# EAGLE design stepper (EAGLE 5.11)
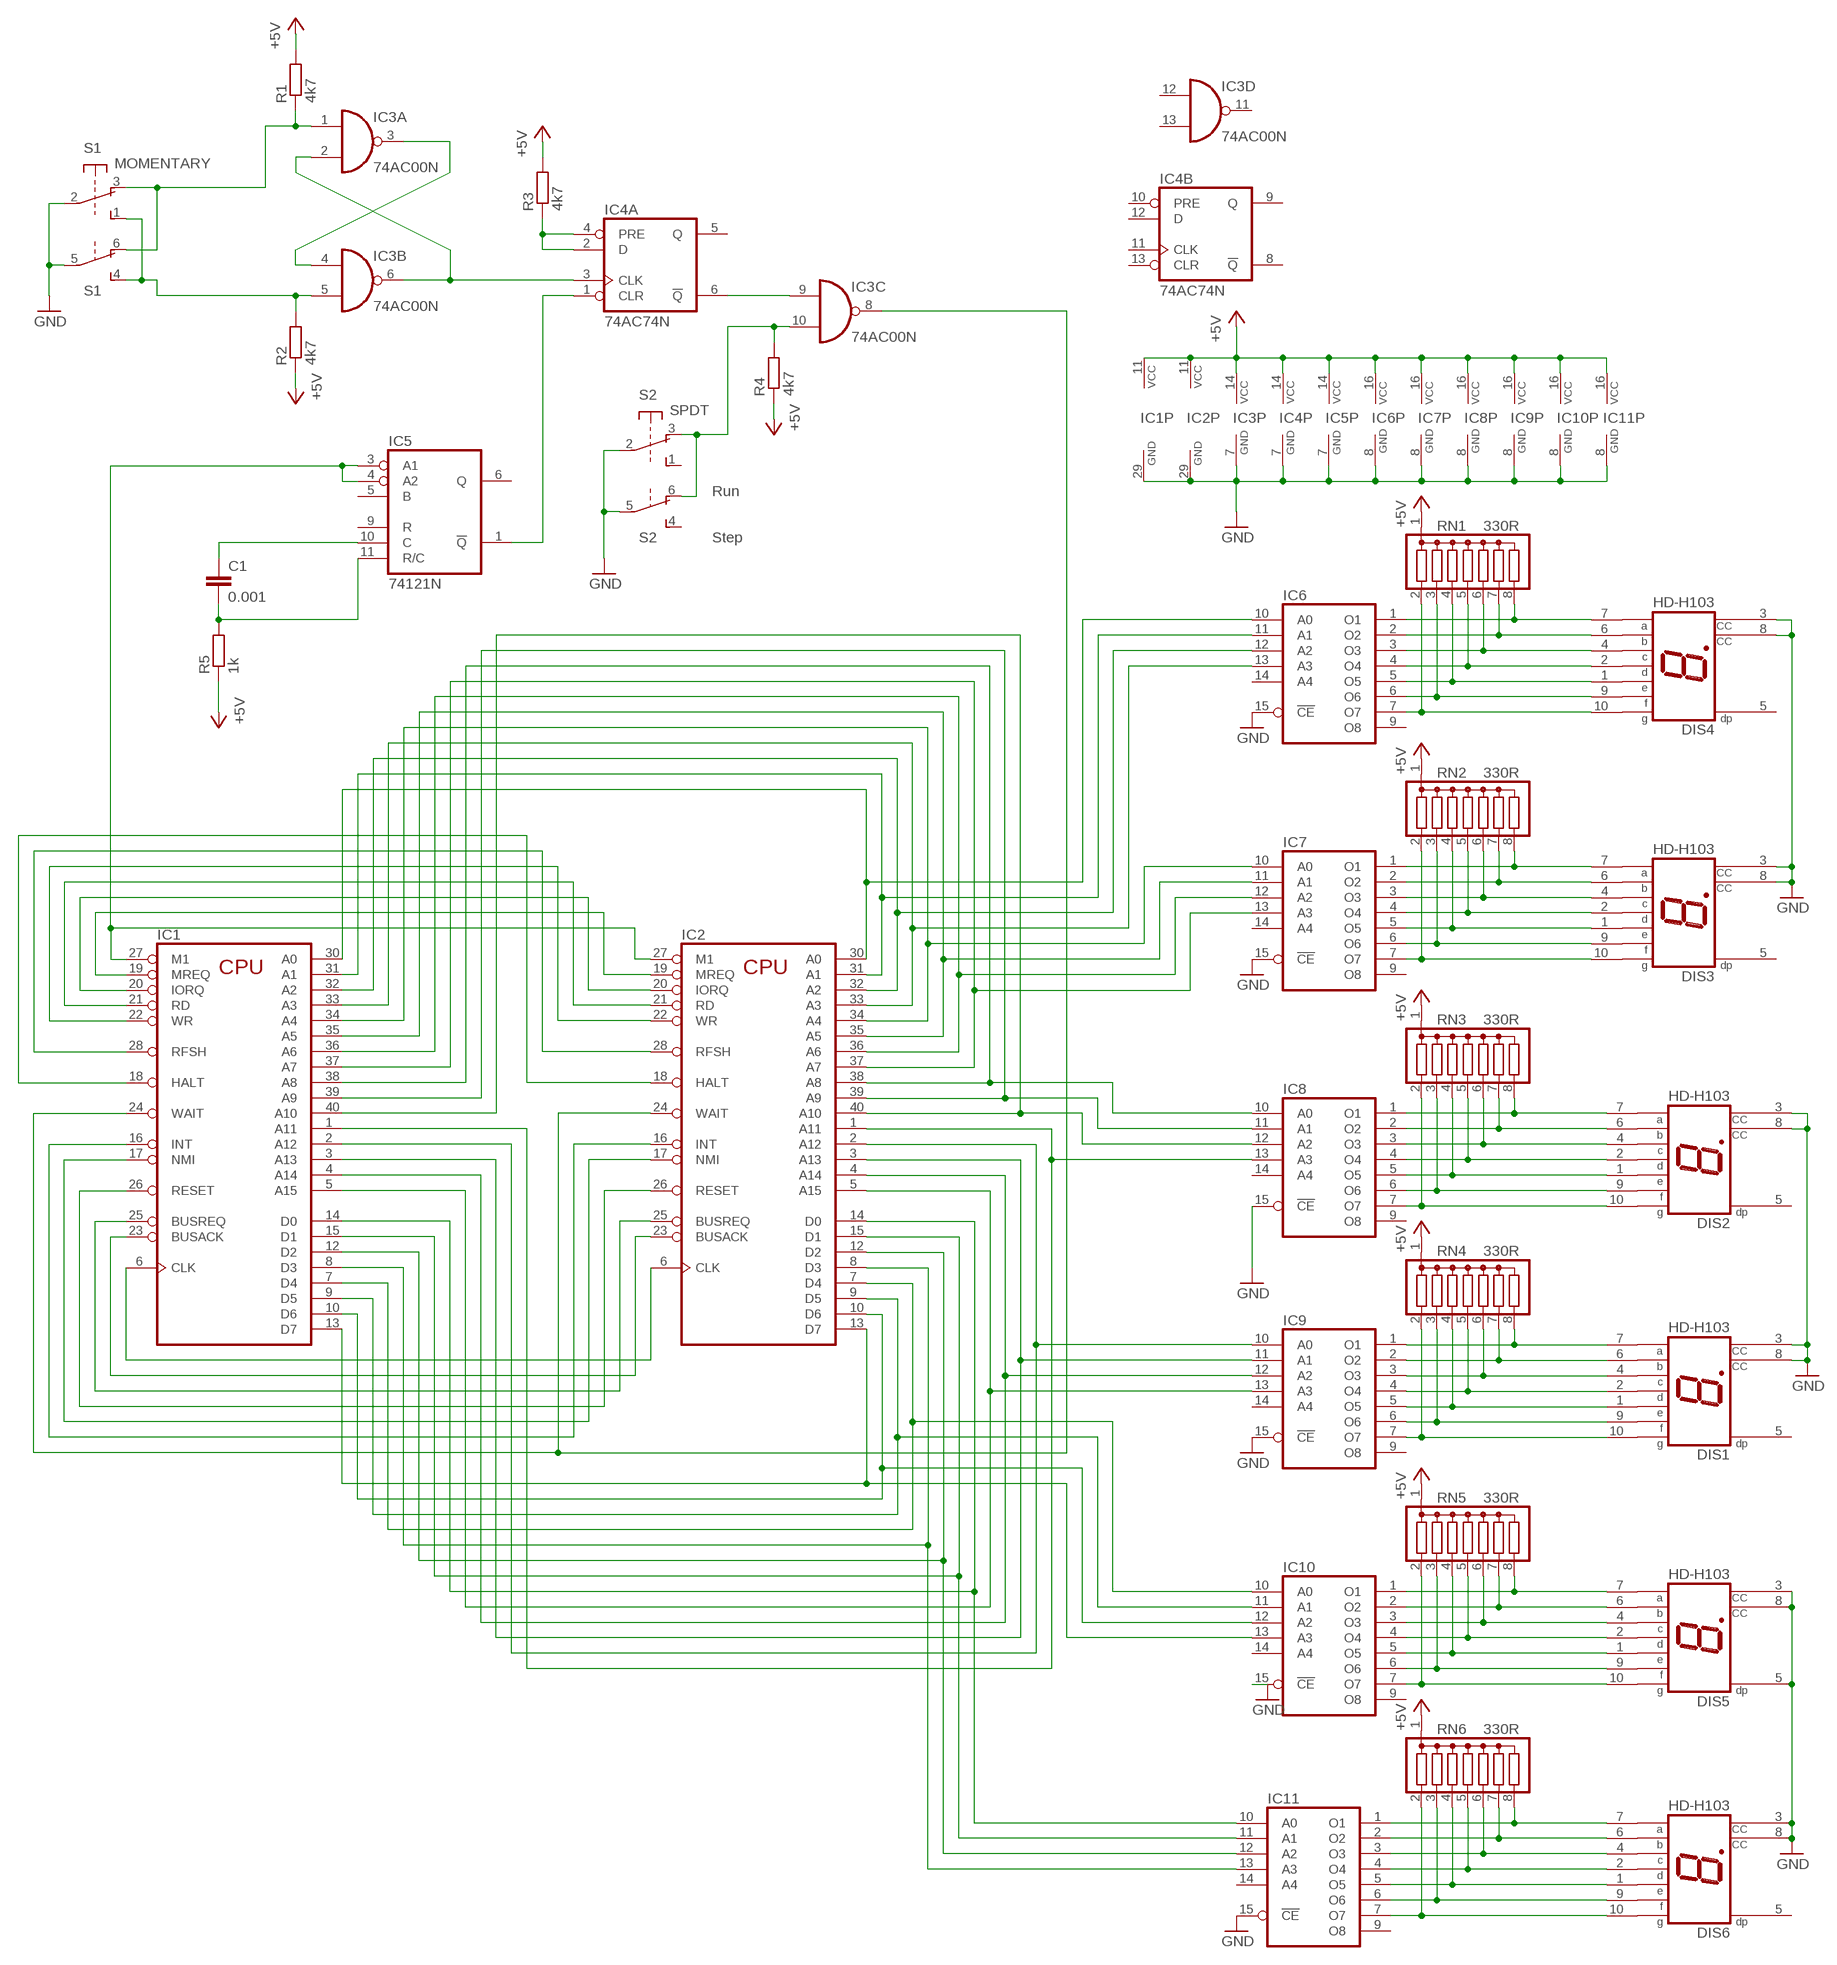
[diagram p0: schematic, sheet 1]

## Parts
C1  0.001  C-EU025-025X050  [C025-025X050]
DIS1  HD-H103  [HDSP-M]
DIS2  HD-H103  [HDSP-M]
DIS3  HD-H103  [HDSP-M]
DIS4  HD-H103  [HDSP-M]
DIS5  HD-H103  [HDSP-M]
DIS6  HD-H103  [HDSP-M]
IC1  Z80CPU-P  [DIP-40]
IC2  Z80CPU-P  [DIP-40]
IC3  74AC00N  [DIL14]
IC4  74AC74N  [DIL14]
IC5  74121N  [DIL14]
IC6  155RE3  [DIL16]
IC7  155RE3  [DIL16]
IC8  155RE3  [DIL16]
IC9  155RE3  [DIL16]
IC10  155RE3  [DIL16]
IC11  155RE3  [DIL16]
R1  4k7  R-EU_0207/10  [0207/10]
R2  4k7  R-EU_0207/10  [0207/10]
R3  4k7  R-EU_0207/10  [0207/10]
R4  4k7  R-EU_0207/10  [0207/10]
R5  1k  R-EU_0207/10  [0207/10]
RN1  330R  G07R  [SIL8]
RN2  330R  G07R  [SIL8]
RN3  330R  G07R  [SIL8]
RN4  330R  G07R  [SIL8]
RN5  330R  G07R  [SIL8]
RN6  330R  G07R  [SIL8]
S1  MOMENTARY  SWITCH(4X4.5MM)  [SWITCH(4X4.5MM)]
S2  SPDT  SWITCH(4X4.5MM)  [SWITCH(4X4.5MM)]

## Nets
+5V: IC1.11(VCC) IC2.11(VCC) IC3.14(P:VCC) IC4.14(P:VCC) IC5.14(VCC) IC6.16(VCC) IC7.16(VCC) IC8.16(VCC) IC9.16(VCC) IC10.16(VCC) IC11.16(VCC) R1.2 R2.1 R3.2 R4.1 R5.1 RN1.1 RN2.1 RN3.1 RN4.1 RN5.1 RN6.1
GND: DIS1.3(CC) DIS1.8(CC) DIS2.3(CC) DIS2.8(CC) DIS3.3(CC) DIS3.8(CC) DIS4.3(CC) DIS4.8(CC) DIS5.3(CC) DIS5.5(DP) DIS5.8(CC) DIS6.3(CC) DIS6.8(CC) IC1.29(GND) IC2.29(GND) IC3.7(P:GND) IC4.7(P:GND) IC5.7(GND) IC6.8(GND) IC6.15(!CE) IC7.8(GND) IC7.15(!CE) IC8.8(GND) IC8.15(!CE) IC9.8(GND) IC9.15(!CE) IC10.8(GND) IC10.15(!CE) IC11.8(GND) IC11.15(!CE) S1.2(1:P) S1.5(2:P) S2.2(1:P) S2.5(2:P)
N$1: IC1.30(A0) IC2.30(A0) IC6.10(A0)
N$2: IC1.31(A1) IC2.31(A1) IC6.11(A1)
N$3: IC1.32(A2) IC2.32(A2) IC6.12(A2)
N$4: IC1.33(A3) IC2.33(A3) IC6.13(A3)
N$5: IC1.34(A4) IC2.34(A4) IC7.10(A0)
N$6: IC1.35(A5) IC2.35(A5) IC7.11(A1)
N$7: IC1.36(A6) IC2.36(A6) IC7.12(A2)
N$8: IC1.37(A7) IC2.37(A7) IC7.13(A3)
N$9: IC1.38(A8) IC2.38(A8) IC8.10(A0)
N$10: IC1.39(A9) IC2.39(A9) IC8.11(A1)
N$11: IC1.40(A10) IC2.40(A10) IC8.12(A2)
N$13: IC1.2(A12) IC2.2(A12) IC9.10(A0)
N$14: IC1.3(A13) IC2.3(A13) IC9.11(A1)
N$15: IC1.4(A14) IC2.4(A14) IC9.12(A2)
N$16: IC1.5(A15) IC2.5(A15) IC9.13(A3)
N$17: IC1.14(D0) IC2.14(D0) IC11.10(A0)
N$18: IC1.15(D1) IC2.15(D1) IC11.11(A1)
N$19: IC1.12(D2) IC2.12(D2) IC11.12(A2)
N$20: IC1.8(D3) IC2.8(D3) IC11.13(A3)
N$21: IC1.7(D4) IC2.7(D4) IC10.10(A0)
N$22: IC1.9(D5) IC2.9(D5) IC10.11(A1)
N$23: IC1.10(D6) IC2.10(D6) IC10.12(A2)
N$24: IC1.13(D7) IC2.13(D7) IC10.13(A3)
N$25: IC1.27(M1) IC2.27(M1) IC5.3(A1) IC5.4(A2)
N$26: IC1.19(MREQ) IC2.19(MREQ)
N$27: IC1.20(IORQ) IC2.20(IORQ)
N$28: IC1.21(RD) IC2.21(RD)
N$29: IC1.22(WR) IC2.22(WR)
N$30: IC1.28(RFSH) IC2.28(RFSH)
N$31: IC1.18(HALT) IC2.18(HALT)
N$32: IC1.24(WAIT) IC2.24(WAIT) IC3.8(C:O)
N$33: IC1.16(INT) IC2.16(INT)
N$34: IC1.17(NMI) IC2.17(NMI)
N$35: IC1.26(RESET) IC2.26(RESET)
N$36: IC1.25(BUSREQ) IC2.25(BUSREQ)
N$37: IC1.23(BUSACK) IC2.23(BUSACK)
N$38: IC1.6(CLK) IC2.6(CLK)
N$39: IC3.2(A:I1) IC3.6(B:O) IC4.3(A:CLK)
N$40: IC3.3(A:O) IC3.4(B:I0)
N$41: IC3.1(A:I0) R1.1 S1.3(1:O) S1.6(2:O)
N$42: IC3.5(B:I1) R2.2 S1.1(1:S) S1.4(2:S)
N$43: IC4.1(A:CLR) IC5.1(!Q)
N$44: IC4.2(A:D) IC4.4(A:PRE) R3.1
N$45: IC3.9(C:I0) IC4.6(A:!Q)
N$46: DIS1.1(E) IC9.5(O5) RN4.4
N$47: IC3.10(C:I1) R4.2 S2.3(1:O) S2.6(2:O)
N$48: C1.1 IC5.10(C)
N$49: C1.2 IC5.11(R/C) R5.2
N$50: DIS1.2(D) IC9.4(O4) RN4.5
N$51: DIS1.4(C) IC9.3(O3) RN4.6
N$52: DIS1.6(B) IC9.2(O2) RN4.7
N$53: DIS1.7(A) IC9.1(O1) RN4.8
N$54: DIS1.10(G) IC9.7(O7) RN4.2
N$55: DIS1.9(F) IC9.6(O6) RN4.3
N$56: DIS2.10(G) IC8.7(O7) RN3.2
N$57: DIS2.9(F) IC8.6(O6) RN3.3
N$58: DIS2.2(D) IC8.4(O4) RN3.5
N$59: DIS2.6(B) IC8.2(O2) RN3.7
N$60: DIS2.7(A) IC8.1(O1) RN3.8
N$61: DIS2.4(C) IC8.3(O3) RN3.6
N$62: DIS2.1(E) IC8.5(O5) RN3.4
N$63: DIS3.10(G) IC7.7(O7) RN2.2
N$64: DIS3.9(F) IC7.6(O6) RN2.3
N$65: DIS3.2(D) IC7.4(O4) RN2.5
N$66: DIS3.6(B) IC7.2(O2) RN2.7
N$67: DIS3.7(A) IC7.1(O1) RN2.8
N$68: DIS3.4(C) IC7.3(O3) RN2.6
N$69: DIS3.1(E) IC7.5(O5) RN2.4
N$70: DIS4.10(G) IC6.7(O7) RN1.2
N$71: DIS4.9(F) IC6.6(O6) RN1.3
N$72: DIS4.2(D) IC6.4(O4) RN1.5
N$73: DIS4.6(B) IC6.2(O2) RN1.7
N$74: DIS4.7(A) IC6.1(O1) RN1.8
N$75: DIS4.4(C) IC6.3(O3) RN1.6
N$76: DIS4.1(E) IC6.5(O5) RN1.4
N$77: DIS5.10(G) IC10.7(O7) RN5.2
N$78: DIS5.9(F) IC10.6(O6) RN5.3
N$79: DIS5.2(D) IC10.4(O4) RN5.5
N$80: DIS5.6(B) IC10.2(O2) RN5.7
N$81: DIS5.7(A) IC10.1(O1) RN5.8
N$82: DIS5.4(C) IC10.3(O3) RN5.6
N$83: DIS5.1(E) IC10.5(O5) RN5.4
N$84: DIS6.10(G) IC11.7(O7) RN6.2
N$85: DIS6.9(F) IC11.6(O6) RN6.3
N$86: DIS6.2(D) IC11.4(O4) RN6.5
N$87: DIS6.6(B) IC11.2(O2) RN6.7
N$88: DIS6.7(A) IC11.1(O1) RN6.8
N$89: DIS6.4(C) IC11.3(O3) RN6.6
N$90: DIS6.1(E) IC11.5(O5) RN6.4
N$91: IC1.1(A11) IC2.1(A11) IC8.13(A3)
Unconnected: DIS1.5(DP) DIS2.5(DP) DIS3.5(DP) DIS4.5(DP) DIS6.5(DP) IC3.11(D:O) IC3.12(D:I0) IC3.13(D:I1) IC4.5(A:Q) IC4.8(B:!Q) IC4.9(B:Q) IC4.10(B:PRE) IC4.11(B:CLK) IC4.12(B:D) IC4.13(B:CLR) IC5.5(B) IC5.6(Q) IC5.9(R) IC6.9(O8) IC6.14(A4) IC7.9(O8) IC7.14(A4) IC8.9(O8) IC8.14(A4) IC9.9(O8) IC9.14(A4) IC10.9(O8) IC10.14(A4) IC11.9(O8) IC11.14(A4) S2.1(1:S) S2.4(2:S)

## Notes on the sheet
- Run
- Step

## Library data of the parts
C1 = rcl:C-EU: CAPACITOR, European symbol
DIS1-DIS6 = display-hp:HD-H103: LED DISPLAY 1-character 7 segment, decimal point right; OC_FARNELL: unknown; OC_NEWARK: unknown
IC1 IC2 = Z80FAMIL:Z80CPU-P
IC3 = 74xx-eu:74*00: Quad 2-input NAND gate
IC4 = 74xx-eu:74*74: Dual D type positive edge triggered FLIP FLOP, preset and clear
IC5 = 74xx-eu:74*121: Monostable MULTIVIBRATOR, schmitt trigger inputs
IC6-IC11 = alex1:155RE3: MEMORY
R1-R5 = rcl:R-EU_: RESISTOR, European symbol
RN1-RN6 = resistor-sil:G07R: SIL RESISTOR; OC_FARNELL: unknown; OC_NEWARK: unknown
S1 S2 = alex1:SWITCH(4X4.5MM): MARQUARDT SWITCH

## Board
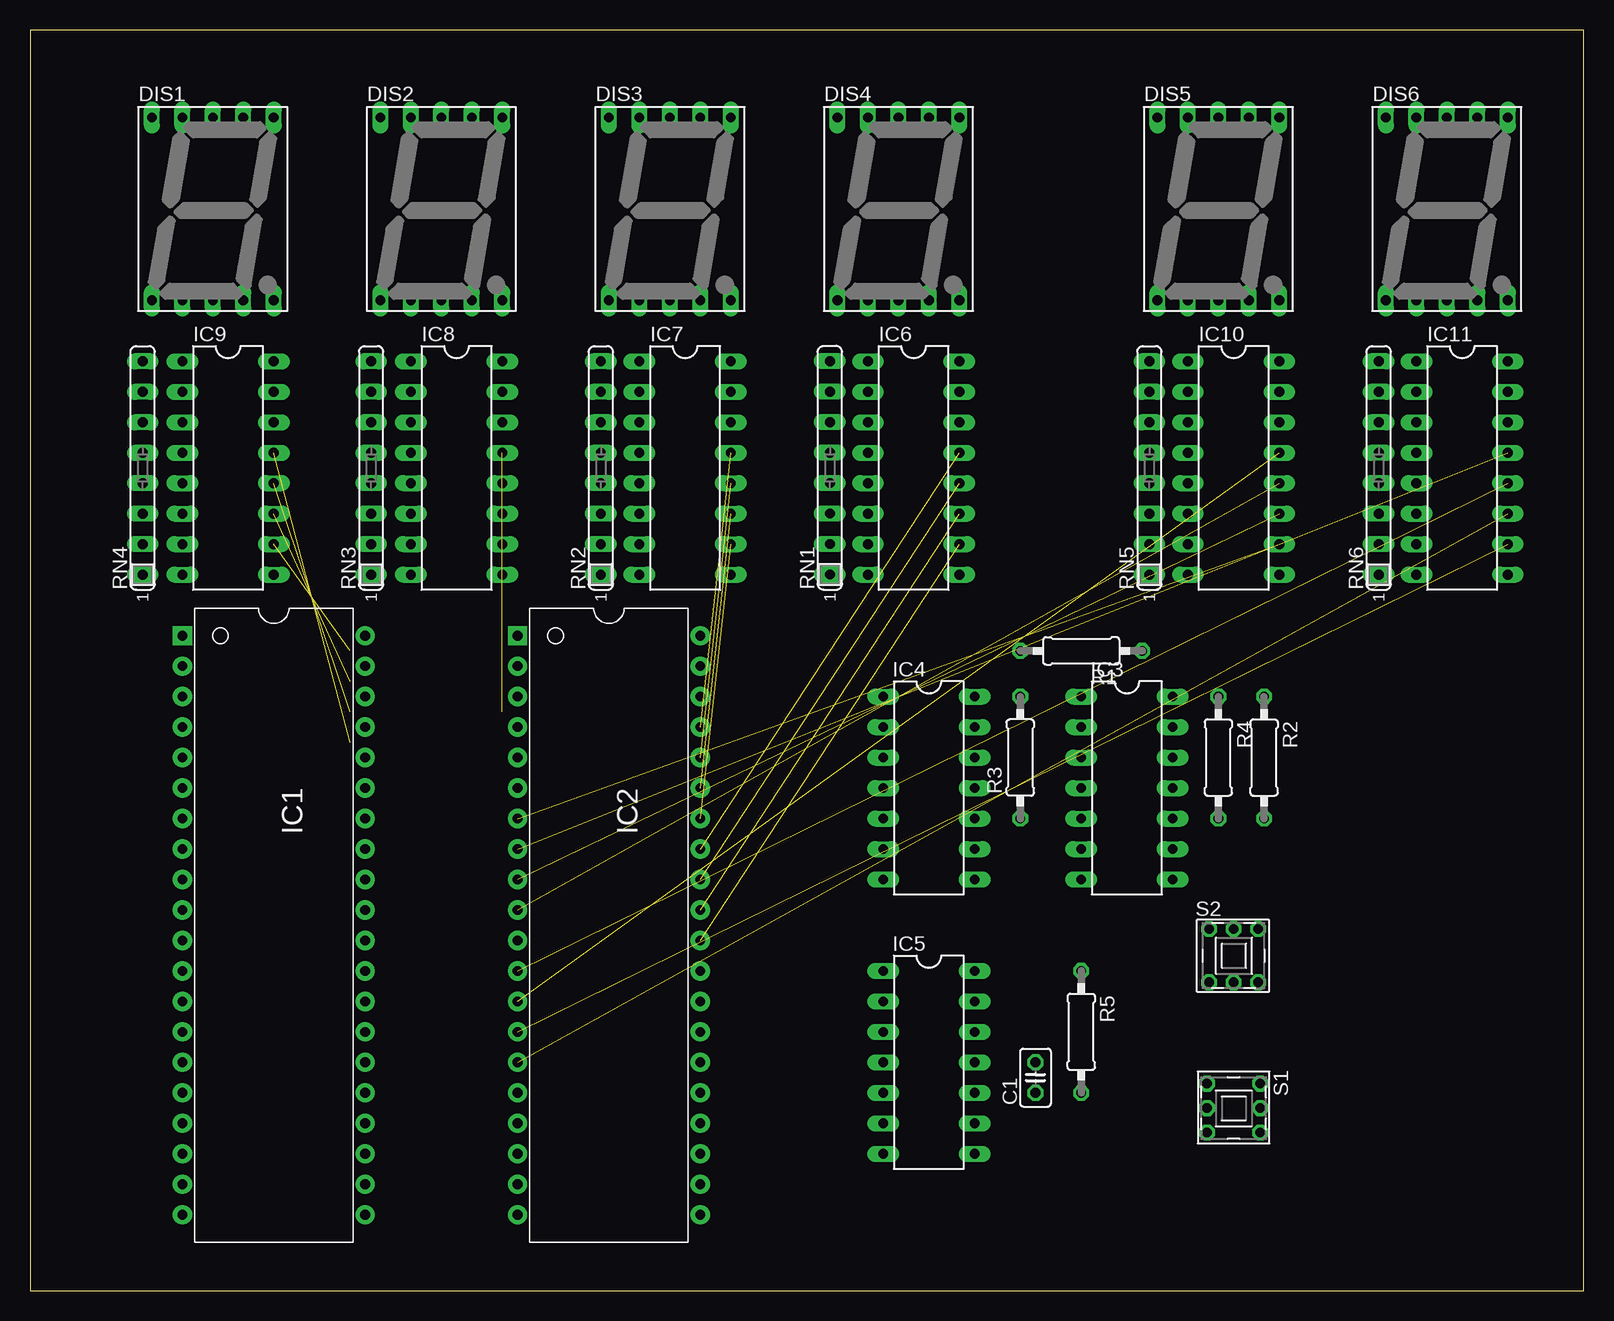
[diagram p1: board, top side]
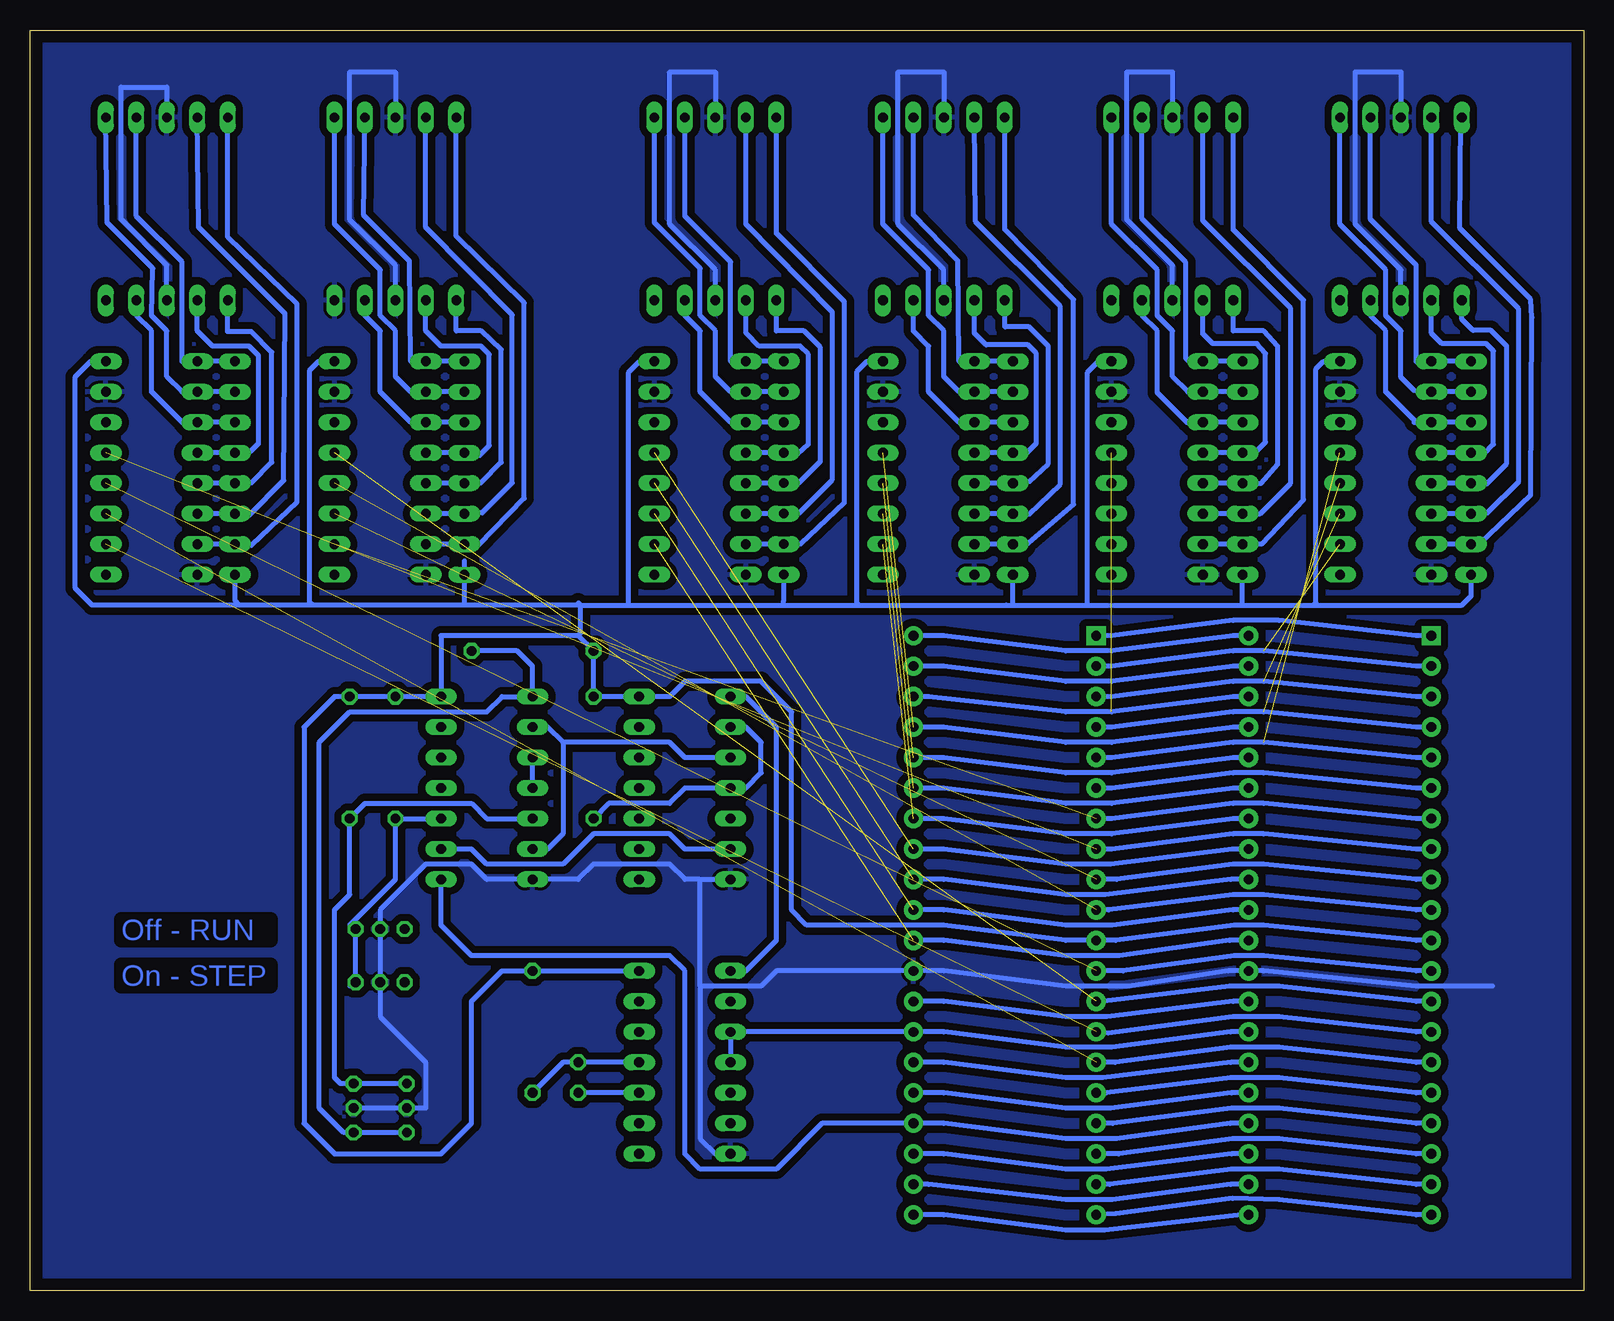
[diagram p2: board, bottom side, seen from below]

Size 129.52 x 105.08 mm. Coordinates in mm from the lower left corner, seen from the top.
Outline: 0,0 129.52,0 129.52,105.08 0,105.08 0,0
Copper layers (1*16): Top 0.035mm / dielectric 1.5mm / Bottom 0.035mm
Design rules "default": minimum track width 10mil, minimum drill 24mil, track to track 8mil, track to pad 8mil, pad to pad 8mil, via to via 8mil, smd to smd 8mil, copper to edge 40mil, drill to drill 8mil, minimum pad ring 10mil, minimum via ring 8mil, stop-mask expansion 4mil, vias tented up to drill 0mil, thermal gap 10mil

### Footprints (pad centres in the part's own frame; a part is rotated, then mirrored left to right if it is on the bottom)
C025-025X050 = drill 0.813 octagon: 1 -1.27,0; 2 1.27,0
HDSP-M = drill 0.813 long: 1 -5.08,-7.62; 2 -2.54,-7.62; 3 0,-7.62; 4 2.54,-7.62; 5 5.08,-7.62; 6 5.08,7.62; 7 2.54,7.62; 8 0,7.62; 9 -2.54,7.62; 10 -5.08,7.62
DIP-40 = drill 0.813 pad 1.6 square: 1 -24.13,-7.62 | drill 0.813 pad 1.6 round: 2 -21.59,-7.62; 3 -19.05,-7.62; 4 -16.51,-7.62; 5 -13.97,-7.62; 6 -11.43,-7.62; 7 -8.89,-7.62; 8 -6.35,-7.62; 9 -3.81,-7.62; 10 -1.27,-7.62; 11 1.27,-7.62; 12 3.81,-7.62; 13 6.35,-7.62; 14 8.89,-7.62; 15 11.43,-7.62; 16 13.97,-7.62; 17 16.51,-7.62; 18 19.05,-7.62; 19 21.59,-7.62; 20 24.13,-7.62; 21 24.13,7.62; 22 21.59,7.62; 23 19.05,7.62; 24 16.51,7.62; 25 13.97,7.62; 26 11.43,7.62; 27 8.89,7.62; 28 6.35,7.62; 29 3.81,7.62; 30 1.27,7.62; 31 -1.27,7.62; 32 -3.81,7.62; 33 -6.35,7.62; 34 -8.89,7.62; 35 -11.43,7.62; 36 -13.97,7.62; 37 -16.51,7.62; 38 -19.05,7.62; 39 -21.59,7.62; 40 -24.13,7.62
DIL14 = drill 0.813 long: 1 -7.62,-3.81; 2 -5.08,-3.81; 3 -2.54,-3.81; 4 0,-3.81; 5 2.54,-3.81; 6 5.08,-3.81; 7 7.62,-3.81; 8 7.62,3.81; 9 5.08,3.81; 10 2.54,3.81; 11 0,3.81; 12 -2.54,3.81; 13 -5.08,3.81; 14 -7.62,3.81
DIL16 = drill 0.813 long: 1 -8.89,-3.81; 2 -6.35,-3.81; 3 -3.81,-3.81; 4 -1.27,-3.81; 5 1.27,-3.81; 6 3.81,-3.81; 7 6.35,-3.81; 8 8.89,-3.81; 9 8.89,3.81; 10 6.35,3.81; 11 3.81,3.81; 12 1.27,3.81; 13 -1.27,3.81; 14 -3.81,3.81; 15 -6.35,3.81; 16 -8.89,3.81
0207/10 = drill 0.813 octagon: 1 -5.08,0; 2 5.08,0
SIL8 = drill 0.813 long: 1 -8.89,0; 2 -6.35,0; 3 -3.81,0; 4 -1.27,0; 5 1.27,0; 6 3.81,0; 7 6.35,0; 8 8.89,0
SWITCH(4X4.5MM) = drill 0.813 octagon: 1 -2.04,-2.22; 2 0,-2.22; 3 2.04,-2.22; 4 -2.04,2.22; 5 0,2.22; 6 2.04,2.22

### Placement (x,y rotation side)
C1  83.82,17.78 90 top
DIS1  15.24,90.17 0 top
DIS2  34.29,90.17 0 top
DIS3  53.34,90.17 0 top
DIS4  72.39,90.17 0 top
DIS5  99.06,90.17 0 top
DIS6  118.11,90.17 0 top
IC1  20.32,30.48 270 top
IC2  48.26,30.48 270 top
IC3  91.44,41.91 270 top
IC4  74.93,41.91 270 top
IC5  74.93,19.05 270 top
IC6  73.66,68.58 270 top
IC7  54.61,68.58 270 top
IC8  35.56,68.58 270 top
IC9  16.51,68.58 270 top
IC10  100.33,68.58 270 top
IC11  119.38,68.58 270 top
R1  87.63,53.34 180 top
R2  102.87,44.45 270 top
R3  82.55,44.45 90 top
R4  99.06,44.45 270 top
R5  87.63,21.59 270 top
RN1  66.68,68.59 90 top
RN2  47.59,68.58 90 top
RN3  28.44,68.58 90 top
RN4  9.39,68.58 90 top
RN5  93.31,68.58 90 top
RN6  112.43,68.58 90 top
S1  100.33,15.24 270 top
S2  100.33,27.94 0 top

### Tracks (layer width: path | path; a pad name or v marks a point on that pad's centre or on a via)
+5V
  Bottom 0.406: IC1.11 13.97,29.21 26.67,30.48 29.13,30.48 39.01,29.21 IC2.11 43.18,29.21 53.34,30.48 64.77,30.48 66.04,31.75 66.04,48.26 68.58,50.8 74.93,50.8 76.2,49.53 IC4.14 R3.2 R1.2 83.82,54.61 | IC5.14 R5.1 90.17,26.67 92.71,24.13 92.71,13.97 95.25,11.43 104.14,11.43 106.68,13.97 106.68,46.99 104.14,49.53 R2.1 R4.1 IC3.14 95.25,54.61 83.82,54.61 | IC8.16 40.44,77.47 41.37,76.54 41.37,57.21 41.43,57.15 | IC7.16 59.75,77.47 60.58,76.64 60.58,57.3 60.43,57.15 | IC6.16 78.69,77.47 79.62,76.54 79.62,57.16 79.63,57.15 | IC11.16 124.46,77.47 125.73,76.2 125.73,58.54 124.34,57.15 112.03,57.15 | IC10.16 105.46,77.47 106.19,76.74 106.19,57.41 105.93,57.15 | 93.33,60.84 93.31,60.82 RN5.1 93.31,57.23 93.23,57.15 | RN4.1 9.39,57.92 10.16,57.15 22.53,57.15 | 28.43,57.15 22.53,57.15 | 41.43,57.15 28.43,57.15 | 48.13,57.15 41.43,57.15 | 60.43,57.15 48.13,57.15 | 66.73,57.15 60.43,57.15 | 79.63,57.15 66.73,57.15 | 83.63,57.15 79.63,57.15 | 83.63,57.15 93.23,57.15 | 93.23,57.15 105.93,57.15 | IC9.16 21.7,77.47 22.33,76.84 22.33,57.35 22.53,57.15 | RN3.1 28.44,57.16 28.43,57.15 | RN2.1 47.59,57.19 48.13,57.15 | RN1.1 66.68,57.6 66.73,57.15 | 83.63,57.15 83.82,57.34 | 83.63,57.15 83.63,54.8 83.82,54.61 | 105.93,57.15 112.03,57.15 | RN6.1 112.43,57.55 112.03,57.15
GND
  Bottom 0.406: 73.66,34.29 IC4.7 | 73.66,34.29 74.93,34.29 76.2,35.56 82.55,35.56 83.82,34.29 IC3.7 91.44,34.29 92.71,35.56 96.52,35.56 100.33,31.75 S2.5 S2.2 100.33,22.86 96.52,19.05 96.52,15.24 S1.2 S1.5 | 73.66,25.4 68.58,25.4 67.31,26.67 IC2.29 53.34,26.67 43.18,25.4 37.91,25.4 29.63,26.67 IC1.29 26.67,26.67 13.97,25.4 7.62,25.4 | 73.66,25.4 73.66,34.29 | IC5.7 72.39,11.43 73.66,12.7 73.66,25.4 | DIS1.3 15.24,85.09 19.05,88.9 19.05,101.6 15.24,101.6 DIS1.8 | DIS2.3 34.29,85.46 38.1,89.27 38.1,101.6 34.29,101.6 DIS2.8 | DIS3.3 53.34,85.09 57.15,88.9 57.15,101.6 53.34,101.6 DIS3.8 | DIS4.3 72.39,85.09 76.2,88.9 76.2,101.6 72.39,101.6 DIS4.8 | DIS5.3 99.06,85.46 102.87,89.27 102.87,101.6 99.06,101.6 DIS5.8 | DIS6.3 118.11,85.49 121.92,89.3 121.92,100.33 118.11,100.33 DIS6.8
  pour Bottom (isolate 0.61): 0,105.41 129.54,105.41 129.54,0 0,0
N$1  (1 unrouted)
  Bottom 0.406: IC1.30 29.53,29.21 38.71,27.94 43.18,27.94 53.34,29.21 IC2.30
N$2  (1 unrouted)
  Bottom 0.406: IC1.31 29.23,31.75 39.31,30.48 43.18,30.48 53.34,31.75 IC2.31
N$3  (1 unrouted)
  Bottom 0.406: IC1.32 29.43,34.29 39.91,33.02 43.18,33.02 53.34,34.29 IC2.32
N$4  (1 unrouted)
  Bottom 0.406: IC1.33 29.33,36.83 39.44,35.56 43.18,35.56 53.34,36.83 IC2.33
N$5  (1 unrouted)
  Bottom 0.406: IC1.34 29.21,39.37 39.37,38.1 43.18,38.1 53.34,39.37 IC2.34
N$6  (1 unrouted)
  Bottom 0.406: IC1.35 29.21,41.91 39.37,40.64 43.18,40.64 53.34,41.91 IC2.35
N$7  (1 unrouted)
  Bottom 0.406: IC1.36 29.21,44.45 39.37,43.18 43.18,43.18 53.34,44.45 IC2.36
N$8  (1 unrouted)
  Bottom 0.406: IC1.37 29.21,46.99 39.37,45.72 43.18,45.72 53.34,46.99 IC2.37
N$9  (1 unrouted)
  Bottom 0.406: IC1.38 29.21,49.53 39.37,48.26 43.18,48.26 54.61,49.53 IC2.38
N$10  (1 unrouted)
  Bottom 0.406: IC1.39 29.21,52.07 39.37,50.8 43.18,50.8 53.34,52.07 IC2.39
N$11  (1 unrouted)
  Bottom 0.406: IC1.40 29.21,54.61 39.37,53.34 43.18,53.34 53.34,54.61 IC2.40
N$13  (1 unrouted)
  Bottom 0.406: IC2.2 39.37,52.07 29.21,53.34 26.67,53.34 13.97,52.07 IC1.2
N$14  (1 unrouted)
  Bottom 0.406: IC1.3 13.97,49.53 26.67,50.8 29.21,50.8 39.37,49.53 IC2.3
N$15  (1 unrouted)
  Bottom 0.406: IC1.4 13.97,46.99 26.67,48.26 29.21,48.26 39.37,46.99 IC2.4
N$16  (1 unrouted)
  Bottom 0.406: IC1.5 13.97,44.45 26.67,45.72 29.21,45.72 39.37,44.45 IC2.5
N$17  (1 unrouted)
  Bottom 0.406: IC1.14 13.97,21.59 25.4,22.86 29.23,22.86 39.65,21.49 IC2.14
N$18  (1 unrouted)
  Bottom 0.406: IC1.15 13.97,19.05 25.4,20.32 29.43,20.32 39.05,19.05 IC2.15
N$19  (1 unrouted)
  Bottom 0.406: IC1.12 13.97,26.67 26.67,27.94 29.13,27.94 38.41,26.67 IC2.12
N$20  (1 unrouted)
  Bottom 0.406: IC1.8 13.97,36.83 26.67,38.1 29.21,38.1 39.37,36.83 IC2.8
N$21  (1 unrouted)
  Bottom 0.406: IC1.7 13.97,39.37 26.67,40.64 29.21,40.64 39.37,39.37 IC2.7
N$22  (1 unrouted)
  Bottom 0.406: IC1.9 13.97,34.29 26.67,35.56 29.23,35.56 38.94,34.29 IC2.9
N$23  (1 unrouted)
  Bottom 0.406: IC1.10 13.97,31.75 26.67,33.02 29.23,33.02 39.61,31.75 IC2.10
N$24  (1 unrouted)
  Bottom 0.406: IC1.13 13.97,24.13 25.4,25.4 29.53,25.4 40.05,24.13 IC2.13
N$25
  Bottom 0.406: IC1.27 29.43,21.59 39.35,20.32 43.18,20.32 53.34,21.59 IC2.27 IC5.3 IC5.4
N$26
  Bottom 0.406: IC1.19 13.97,8.89 25.4,10.16 29.38,10.16 39.54,8.89 IC2.19
N$27
  Bottom 0.406: IC1.20 13.97,6.35 25.4,7.62 29.26,7.72 39.02,6.45 IC2.20
N$28
  Bottom 0.406: IC1.21 28.51,6.35 39.94,5.08 43.18,5.08 53.34,6.35 IC2.21
N$29
  Bottom 0.406: IC1.22 29.43,8.89 39.32,7.62 43.18,7.62 54.61,8.89 IC2.22
N$30
  Bottom 0.406: IC1.28 29.23,24.13 39.75,22.86 43.18,22.86 53.34,24.13 IC2.28
N$31
  Bottom 0.406: IC1.18 13.97,11.43 25.4,12.7 29.26,12.7 38.75,11.43 IC2.18
N$32
  Bottom 0.406: IC1.24 29.46,13.97 38.95,12.7 43.18,12.7 53.34,13.97 IC2.24 63.5,13.97 67.31,10.16 73.66,10.16 74.93,11.43 74.93,26.67 76.2,27.94 92.71,27.94 95.25,30.48 IC3.8
N$33
  Bottom 0.406: IC1.16 13.97,16.51 25.4,17.78 29.43,17.78 39.82,16.51 IC2.16
N$34
  Bottom 0.406: IC1.17 13.97,13.97 25.4,15.24 29.36,15.24 39.25,13.97 IC2.17
N$35
  Bottom 0.406: IC1.26 29.43,19.05 40.12,17.78 43.18,17.78 53.34,19.05 IC2.26
N$36
  Bottom 0.406: IC1.25 29.36,16.51 39.45,15.24 43.18,15.24 53.34,16.51 IC2.25
N$37
  Bottom 0.406: IC1.23 29.36,11.43 39.82,10.16 43.18,10.16 53.34,11.43 IC2.23
N$38
  Bottom 0.406: IC1.6 13.97,41.91 26.67,43.18 29.21,43.18 39.37,41.91 IC2.6
N$39
  Bottom 0.406: IC4.3 74.93,44.45 76.2,45.72 85.09,45.72 | 85.09,45.72 86.36,46.99 IC3.2 | IC3.6 86.36,36.83 85.09,38.1 85.09,45.72
N$40
  Bottom 0.406: IC3.4 IC3.3
N$41
  Bottom 0.406: R1.1 88.9,53.34 87.63,52.07 IC3.1 90.17,49.53 91.44,48.26 102.87,48.26 105.41,45.72 105.41,15.24 103.37,13.2 S1.6 S1.3
N$42
  Bottom 0.406: IC3.5 91.44,39.37 92.71,40.64 101.6,40.64 R2.2 102.87,33.02 104.14,31.75 104.14,17.78 103.64,17.28 S1.4 S1.1
N$43
  Bottom 0.406: IC4.1 69.85,49.53 67.31,46.99 67.31,29.21 69.85,26.67 IC5.1
N$44
  Bottom 0.406: IC4.2 69.85,46.99 68.58,45.72 68.58,43.18 69.85,41.91 IC4.4 74.93,41.91 76.2,40.64 81.28,40.64 R3.1
N$45
  Bottom 0.406: IC4.6 74.93,36.83 76.2,38.1 82.55,38.1 85.09,35.56 91.44,35.56 92.71,36.83 IC3.9
N$46
  Bottom 0.406: IC9.5 RN4.4 9.32,67.24 8.13,67.24 6.43,68.94 6.43,78.74 7.73,80.04 9.23,80.04 10.16,80.97 DIS1.1
N$47
  Bottom 0.406: S2.3 102.69,25.4 102.87,25.4 102.37,25.9 S2.6 102.69,30.48 102.87,30.48 99.06,34.29 R4.2 IC3.10
N$48
  Bottom 0.406: IC5.10 C1.1
N$49
  Bottom 0.406: IC5.11 C1.2 85.09,19.05 R5.2
N$50
  Bottom 0.406: IC9.4 RN4.5 9.28,69.74 8.33,69.74 7.53,70.54 7.53,78.34 8.13,78.94 11.83,78.94 12.7,79.81 DIS1.2
N$51
  Bottom 0.406: 13.97,72.39 IC9.3 RN4.6 | 13.97,72.39 14.14,72.39 | DIS1.4 17.78,81.28 16.51,80.01 16.51,74.93 13.97,72.39
N$52
  Bottom 0.406: DIS1.6 20.32,88.9 16.51,85.09 16.51,81.28 15.24,80.01 15.24,76.13 14.14,75.03 IC9.2 RN4.7
N$53
  Bottom 0.406: DIS1.7 17.78,89.3 13.97,85.49 13.97,77.47 IC9.1 RN4.8
N$54
  Bottom 0.406: IC9.7 RN4.2 8.74,62.23 4.43,66.34 4.33,81.11 4.43,82.64 10.33,88.54 10.23,97.72 DIS1.10
N$55
  Bottom 0.406: IC9.6 RN4.3 9.16,64.54 8.03,64.84 5.43,67.44 5.43,81.84 12.7,89.11 DIS1.9
N$56
  Bottom 0.406: IC8.7 RN3.2 26.87,62.23 23.36,65.94 23.36,82.58 29.21,88.43 DIS2.10
N$57
  Bottom 0.406: IC8.6 RN3.3 26.97,64.77 24.43,67.31 24.43,81.88 31.75,89.2 DIS2.9
N$58
  Bottom 0.406: IC8.4 RN3.5 27.43,69.84 26.53,70.74 26.53,78.14 27.23,78.94 30.93,78.94 31.75,79.76 DIS2.2
N$59
  Bottom 0.406: DIS2.6 39.37,88.9 35.56,85.09 35.56,81.28 34.29,80.01 34.29,76.2 33.02,74.93 IC8.2 RN3.7
N$60
  Bottom 0.406: DIS2.7 36.83,89.37 33.17,85.71 33.17,77.74 32.9,77.47 IC8.1 RN3.8
N$61
  Bottom 0.406: DIS2.4 36.83,81.28 35.56,80.01 35.56,74.86 33.09,72.39 IC8.3 RN3.6
N$62
  Bottom 0.406: IC8.5 RN3.4 26.87,67.31 25.5,68.88 25.5,78.74 26.67,80.01 29.21,80.01 DIS2.1
N$63
  Bottom 0.406: IC7.7 RN2.2 47.5,62.14 46.53,62.14 42.53,65.54 42.53,82.64 48.26,88.47 DIS3.10
N$64
  Bottom 0.406: IC7.6 RN2.3 47.56,64.74 46.23,64.74 43.63,67.24 43.63,82.04 50.7,89.11 DIS3.9
N$65
  Bottom 0.406: IC7.4 RN2.5 46.43,69.84 45.63,70.64 45.63,78.14 46.33,78.84 49.83,78.84 50.8,79.81 DIS3.2
N$66
  Bottom 0.406: DIS3.6 58.42,88.9 54.61,85.09 54.61,81.28 53.34,80.01 53.34,76.2 52.07,74.93 IC7.2 RN2.7
N$67
  Bottom 0.406: DIS3.7 55.88,89.68 52.17,85.87 52.07,77.47 IC7.1 RN2.8
N$68
  Bottom 0.406: DIS3.4 55.88,80.01 54.61,78.74 54.61,74.93 52.07,72.39 IC7.3 RN2.6
N$69
  Bottom 0.406: IC7.5 RN2.4 47.46,67.44 46.23,67.44 44.63,68.94 44.63,78.74 46.23,80.34 48.23,80.34 48.26,80.37 DIS3.1
N$70
  Bottom 0.406: DIS4.10 67.31,88.13 61.63,82.45 61.63,65.67 65.27,62.23 RN1.2 IC6.7
N$71
  Bottom 0.406: DIS4.9 69.85,88.9 62.63,81.58 62.63,67.61 65.47,64.77 RN1.3 IC6.6
N$72
  Bottom 0.406: DIS4.2 69.85,79.86 68.73,78.74 65.33,78.74 64.63,78.04 64.63,70.54 65.53,69.74 66.56,69.74 RN1.5 IC6.4
N$73
  Bottom 0.406: DIS4.6 77.47,89.03 73.66,85.22 73.66,81.28 72.39,80.01 72.39,76.2 71.12,74.93 IC6.2 RN1.7
N$74
  Bottom 0.406: DIS4.7 74.93,89.57 71.12,85.76 71.12,77.47 IC6.1 RN1.8
N$75
  Bottom 0.406: DIS4.4 74.93,81.28 73.66,80.01 73.66,74.93 71.12,72.39 IC6.3 RN1.6
N$76
  Bottom 0.406: DIS4.1 67.31,80.01 65,80.01 63.63,78.64 63.63,69.14 65.43,67.34 66.66,67.34 RN1.4 IC6.5
N$77
  Bottom 0.406: IC10.7 RN5.2 93.22,62.14 92.13,62.14 88.33,66.04 88.33,82.34 93.98,87.89 DIS5.10
N$78
  Bottom 0.406: IC10.6 RN5.3 93.24,64.84 91.83,64.84 89.33,67.34 89.33,81.34 96.52,88.63 DIS5.9
N$79
  Bottom 0.406: DIS5.2 96.52,80.01 95.25,78.74 91.93,78.74 91.23,78.04 91.23,70.44 92.03,69.64 93.1,69.64 RN5.5 IC10.4
N$80
  Bottom 0.406: DIS5.6 104.14,88.9 100.33,85.09 100.33,81.28 99.06,80.01 99.06,76.2 97.79,74.93 IC10.2 RN5.7
N$81
  Bottom 0.406: DIS5.7 101.7,89.64 97.89,85.83 97.79,77.47 IC10.1 RN5.8
N$82
  Bottom 0.406: DIS5.4 101.6,81.28 100.33,80.01 100.33,74.93 97.79,72.39 IC10.3 RN5.6
N$83
  Bottom 0.406: IC10.5 RN5.4 93.28,67.34 91.93,67.34 90.23,69.04 90.23,78.44 91.9,80.01 93.98,80.01 DIS5.1
N$84
  Bottom 0.406: IC11.7 RN6.2 112.34,62.14 111.06,62.14 107.26,65.74 107.26,82.24 113.03,87.81 DIS6.10
N$85
  Bottom 0.406: IC11.6 RN6.3 112.3,64.64 111.26,64.64 108.36,67.54 108.26,81.44 115.47,88.65 DIS6.9
N$86
  Bottom 0.406: IC11.4 RN6.5 112.34,69.94 111.16,69.94 110.46,70.64 110.46,77.94 111.26,78.74 114.3,78.74 115.57,80.01 DIS6.2
N$87
  Bottom 0.406: DIS6.6 123.09,89.03 119.28,85.22 119.38,81.28 118.11,80.01 118.11,76.2 116.84,74.93 IC11.2 RN6.7
N$88
  Bottom 0.406: DIS6.7 120.65,89.57 116.84,85.76 116.84,77.47 IC11.1 RN6.8
N$89
  Bottom 0.406: DIS6.4 120.65,81.28 119.38,80.01 119.38,74.93 116.84,72.39 IC11.3 RN6.6
N$90
  Bottom 0.406: IC11.5 RN6.4 112.4,67.34 111.06,67.34 109.36,69.04 109.36,78.24 111.06,79.94 113.06,79.94 113.03,79.97 DIS6.1
N$91  (1 unrouted)
  Bottom 0.406: IC1.1 13.97,54.61 25.4,55.88 29.21,55.88 39.37,54.61 IC2.1

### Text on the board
Bottom: Off - RUN | On - STEP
